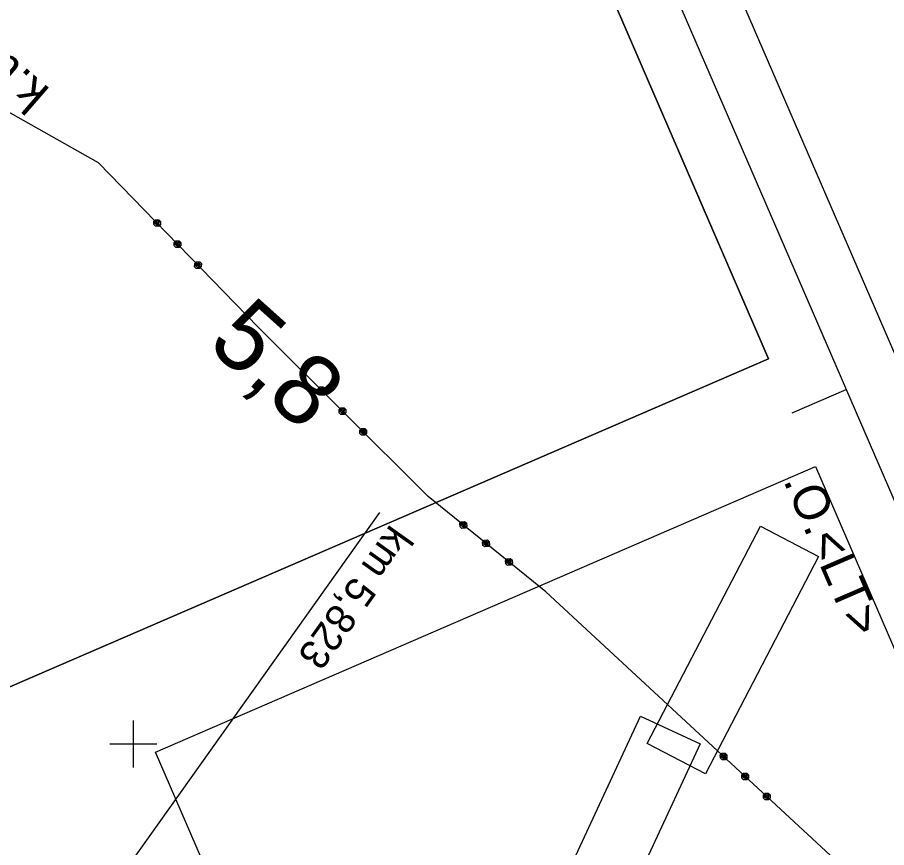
# Model space of a CAD drawing. Extents: x -866402 to -860377, y -1041908 to -1038598.
# Drawn here: x -864609.8 to -864536, y -1041408.8 to -1041338.3 of the extents above; entities that cross this region are included whole.
import ezdxf

# ---------------------------------------------------------------- set-up
doc = ezdxf.new("R2010")
doc.units = 0
for name, color, linetype in [('Vrstva 1', 7, 'Continuous'), ('Vrstva 21', 7, 'Continuous'), ('Vrstva 5', 7, 'Continuous'), ('Vrstva 55', 7, 'Continuous'), ('Vrstva 7', 7, 'Continuous'), ('Vrstva 9', 7, 'Continuous')]:
    doc.layers.add(name, color=color, linetype=linetype)

msp = doc.modelspace()

# ---------------------------------------------------------------- linework, layer by layer
at = {"layer": 'Vrstva 1'}
for p, q in [((-864602.95, -1041350.6), (-864622.98, -1041339.37)), ((-864602.95, -1041350.6), (-864622.98, -1041339.37)), ((-864589.39, -1041364.59), (-864602.95, -1041350.6)), ((-864589.39, -1041364.59), (-864602.95, -1041350.6)), ((-864598.264, -1041355.865), (-864598.26, -1041355.582)), ((-864598.264, -1041355.865), (-864598.26, -1041355.582)), ((-864598.125, -1041356.008), (-864598.264, -1041355.865)), ((-864598.125, -1041356.008), (-864598.264, -1041355.865)), ((-864598.26, -1041355.582), (-864598.116, -1041355.443)), ((-864598.26, -1041355.582), (-864598.116, -1041355.443)), ((-864598.192, -1041355.795), (-864597.905, -1041355.517)), ((-864598.192, -1041355.795), (-864597.905, -1041355.517)), ((-864598.19, -1041355.654), (-864598.192, -1041355.795)), ((-864598.19, -1041355.654), (-864598.192, -1041355.795)), ((-864598.046, -1041355.514), (-864598.19, -1041355.654)), ((-864598.046, -1041355.514), (-864598.19, -1041355.654)), ((-864597.842, -1041356.013), (-864598.125, -1041356.008)), ((-864597.842, -1041356.013), (-864598.125, -1041356.008)), ((-864597.835, -1041355.588), (-864598.123, -1041355.867)), ((-864597.835, -1041355.588), (-864598.123, -1041355.867)), ((-864598.116, -1041355.443), (-864597.833, -1041355.447)), ((-864598.116, -1041355.443), (-864597.833, -1041355.447)), ((-864597.766, -1041355.66), (-864598.053, -1041355.939)), ((-864597.766, -1041355.66), (-864598.053, -1041355.939)), ((-864598.053, -1041355.939), (-864597.912, -1041355.941)), ((-864598.053, -1041355.939), (-864597.912, -1041355.941)), ((-864597.912, -1041355.941), (-864597.768, -1041355.802)), ((-864597.912, -1041355.941), (-864597.768, -1041355.802)), ((-864597.905, -1041355.517), (-864597.766, -1041355.66)), ((-864597.905, -1041355.517), (-864597.766, -1041355.66)), ((-864597.698, -1041355.873), (-864597.842, -1041356.013)), ((-864597.698, -1041355.873), (-864597.842, -1041356.013)), ((-864597.833, -1041355.447), (-864597.694, -1041355.591)), ((-864597.833, -1041355.447), (-864597.694, -1041355.591)), ((-864597.694, -1041355.591), (-864597.698, -1041355.873)), ((-864597.694, -1041355.591), (-864597.698, -1041355.873)), ((-864596.524, -1041357.66), (-864596.52, -1041357.377)), ((-864596.524, -1041357.66), (-864596.52, -1041357.377)), ((-864596.52, -1041357.377), (-864596.376, -1041357.238)), ((-864596.52, -1041357.377), (-864596.376, -1041357.238)), ((-864596.452, -1041357.59), (-864596.165, -1041357.312)), ((-864596.452, -1041357.59), (-864596.165, -1041357.312)), ((-864596.45, -1041357.449), (-864596.452, -1041357.59)), ((-864596.45, -1041357.449), (-864596.452, -1041357.59)), ((-864596.307, -1041357.309), (-864596.45, -1041357.449)), ((-864596.307, -1041357.309), (-864596.45, -1041357.449)), ((-864596.095, -1041357.384), (-864596.383, -1041357.662)), ((-864596.095, -1041357.384), (-864596.383, -1041357.662)), ((-864596.376, -1041357.238), (-864596.093, -1041357.242)), ((-864596.376, -1041357.238), (-864596.093, -1041357.242)), ((-864596.026, -1041357.455), (-864596.313, -1041357.734)), ((-864596.026, -1041357.455), (-864596.313, -1041357.734)), ((-864596.165, -1041357.312), (-864596.026, -1041357.455)), ((-864596.165, -1041357.312), (-864596.026, -1041357.455)), ((-864596.093, -1041357.242), (-864595.954, -1041357.386)), ((-864596.093, -1041357.242), (-864595.954, -1041357.386)), ((-864595.954, -1041357.386), (-864595.959, -1041357.669)), ((-864595.954, -1041357.386), (-864595.959, -1041357.669)), ((-864596.385, -1041357.803), (-864596.524, -1041357.66)), ((-864596.385, -1041357.803), (-864596.524, -1041357.66)), ((-864596.102, -1041357.808), (-864596.385, -1041357.803)), ((-864596.102, -1041357.808), (-864596.385, -1041357.803)), ((-864596.313, -1041357.734), (-864596.172, -1041357.736)), ((-864596.313, -1041357.734), (-864596.172, -1041357.736)), ((-864596.172, -1041357.736), (-864596.028, -1041357.597)), ((-864596.172, -1041357.736), (-864596.028, -1041357.597)), ((-864595.959, -1041357.669), (-864596.102, -1041357.808)), ((-864595.959, -1041357.669), (-864596.102, -1041357.808)), ((-864594.784, -1041359.455), (-864594.78, -1041359.172)), ((-864594.784, -1041359.455), (-864594.78, -1041359.172)), ((-864594.645, -1041359.598), (-864594.784, -1041359.455)), ((-864594.645, -1041359.598), (-864594.784, -1041359.455)), ((-864594.78, -1041359.172), (-864594.636, -1041359.033)), ((-864594.78, -1041359.172), (-864594.636, -1041359.033)), ((-864594.712, -1041359.385), (-864594.425, -1041359.107)), ((-864594.712, -1041359.385), (-864594.425, -1041359.107)), ((-864594.71, -1041359.244), (-864594.712, -1041359.385)), ((-864594.71, -1041359.244), (-864594.712, -1041359.385)), ((-864594.567, -1041359.105), (-864594.71, -1041359.244)), ((-864594.567, -1041359.105), (-864594.71, -1041359.244)), ((-864594.362, -1041359.603), (-864594.645, -1041359.598)), ((-864594.362, -1041359.603), (-864594.645, -1041359.598)), ((-864594.356, -1041359.179), (-864594.643, -1041359.457)), ((-864594.356, -1041359.179), (-864594.643, -1041359.457)), ((-864594.636, -1041359.033), (-864594.353, -1041359.037)), ((-864594.636, -1041359.033), (-864594.353, -1041359.037)), ((-864594.286, -1041359.25), (-864594.573, -1041359.529)), ((-864594.286, -1041359.25), (-864594.573, -1041359.529)), ((-864594.573, -1041359.529), (-864594.432, -1041359.531)), ((-864594.573, -1041359.529), (-864594.432, -1041359.531)), ((-864594.432, -1041359.531), (-864594.288, -1041359.392)), ((-864594.432, -1041359.531), (-864594.288, -1041359.392)), ((-864594.425, -1041359.107), (-864594.286, -1041359.25)), ((-864594.425, -1041359.107), (-864594.286, -1041359.25)), ((-864594.219, -1041359.464), (-864594.362, -1041359.603)), ((-864594.219, -1041359.464), (-864594.362, -1041359.603)), ((-864594.353, -1041359.037), (-864594.214, -1041359.181)), ((-864594.353, -1041359.037), (-864594.214, -1041359.181)), ((-864594.214, -1041359.181), (-864594.219, -1041359.464)), ((-864594.214, -1041359.181), (-864594.219, -1041359.464)), ((-864574.94, -1041378.96), (-864589.39, -1041364.59)), ((-864574.94, -1041378.96), (-864589.39, -1041364.59)), ((-864584.291, -1041369.801), (-864584.15, -1041369.659)), ((-864584.291, -1041369.801), (-864584.15, -1041369.659)), ((-864584.291, -1041370.083), (-864584.291, -1041369.801)), ((-864584.291, -1041370.083), (-864584.291, -1041369.801)), ((-864584.149, -1041370.224), (-864584.291, -1041370.083)), ((-864584.149, -1041370.224), (-864584.291, -1041370.083)), ((-864584.079, -1041369.729), (-864584.22, -1041369.871)), ((-864584.22, -1041370.012), (-864583.938, -1041369.729)), ((-864584.079, -1041369.729), (-864584.22, -1041369.871)), ((-864584.22, -1041370.012), (-864583.938, -1041369.729)), ((-864584.22, -1041369.871), (-864584.22, -1041370.012)), ((-864584.22, -1041369.871), (-864584.22, -1041370.012)), ((-864584.15, -1041369.659), (-864583.867, -1041369.658)), ((-864584.15, -1041369.659), (-864583.867, -1041369.658)), ((-864583.867, -1041369.799), (-864584.149, -1041370.083)), ((-864583.867, -1041369.799), (-864584.149, -1041370.083)), ((-864583.796, -1041369.87), (-864584.078, -1041370.153)), ((-864583.796, -1041369.87), (-864584.078, -1041370.153)), ((-864583.938, -1041369.729), (-864583.796, -1041369.87)), ((-864583.938, -1041369.729), (-864583.796, -1041369.87)), ((-864583.937, -1041370.153), (-864583.796, -1041370.011)), ((-864583.937, -1041370.153), (-864583.796, -1041370.011)), ((-864583.867, -1041369.658), (-864583.726, -1041369.799)), ((-864583.867, -1041369.658), (-864583.726, -1041369.799)), ((-864583.725, -1041370.082), (-864583.866, -1041370.224)), ((-864583.725, -1041370.082), (-864583.866, -1041370.224)), ((-864583.726, -1041369.799), (-864583.725, -1041370.082)), ((-864583.726, -1041369.799), (-864583.725, -1041370.082)), ((-864544.025, -1041371.844), (-864539.44, -1041369.861)), ((-864583.866, -1041370.224), (-864584.149, -1041370.224)), ((-864583.866, -1041370.224), (-864584.149, -1041370.224)), ((-864584.078, -1041370.153), (-864583.937, -1041370.153)), ((-864584.078, -1041370.153), (-864583.937, -1041370.153)), ((-864582.519, -1041371.563), (-864582.378, -1041371.422)), ((-864582.519, -1041371.563), (-864582.378, -1041371.422)), ((-864582.518, -1041371.846), (-864582.519, -1041371.563)), ((-864582.518, -1041371.846), (-864582.519, -1041371.563)), ((-864582.307, -1041371.492), (-864582.448, -1041371.634)), ((-864582.307, -1041371.492), (-864582.448, -1041371.634)), ((-864582.447, -1041371.775), (-864582.165, -1041371.492)), ((-864582.447, -1041371.775), (-864582.165, -1041371.492)), ((-864582.378, -1041371.422), (-864582.095, -1041371.421)), ((-864582.378, -1041371.422), (-864582.095, -1041371.421)), ((-864582.094, -1041371.562), (-864582.376, -1041371.846)), ((-864582.094, -1041371.562), (-864582.376, -1041371.846)), ((-864582.165, -1041371.492), (-864582.023, -1041371.633)), ((-864582.165, -1041371.492), (-864582.023, -1041371.633)), ((-864582.095, -1041371.421), (-864581.953, -1041371.562)), ((-864582.095, -1041371.421), (-864581.953, -1041371.562)), ((-864581.953, -1041371.562), (-864581.952, -1041371.845)), ((-864581.953, -1041371.562), (-864581.952, -1041371.845)), ((-864582.376, -1041371.987), (-864582.518, -1041371.846)), ((-864582.376, -1041371.987), (-864582.518, -1041371.846)), ((-864582.448, -1041371.634), (-864582.447, -1041371.775)), ((-864582.448, -1041371.634), (-864582.447, -1041371.775)), ((-864582.093, -1041371.986), (-864582.376, -1041371.987)), ((-864582.093, -1041371.986), (-864582.376, -1041371.987)), ((-864582.023, -1041371.633), (-864582.306, -1041371.916)), ((-864582.023, -1041371.633), (-864582.306, -1041371.916)), ((-864582.306, -1041371.916), (-864582.164, -1041371.916)), ((-864582.306, -1041371.916), (-864582.164, -1041371.916)), ((-864582.164, -1041371.916), (-864582.023, -1041371.774)), ((-864582.164, -1041371.916), (-864582.023, -1041371.774)), ((-864581.952, -1041371.845), (-864582.093, -1041371.986)), ((-864581.952, -1041371.845), (-864582.093, -1041371.986)), ((-864580.746, -1041373.326), (-864580.605, -1041373.184)), ((-864580.746, -1041373.326), (-864580.605, -1041373.184)), ((-864580.745, -1041373.609), (-864580.746, -1041373.326)), ((-864580.745, -1041373.609), (-864580.746, -1041373.326)), ((-864580.603, -1041373.75), (-864580.745, -1041373.609)), ((-864580.603, -1041373.75), (-864580.745, -1041373.609)), ((-864580.534, -1041373.255), (-864580.675, -1041373.397)), ((-864580.675, -1041373.538), (-864580.393, -1041373.255)), ((-864580.534, -1041373.255), (-864580.675, -1041373.397)), ((-864580.675, -1041373.538), (-864580.393, -1041373.255)), ((-864580.675, -1041373.397), (-864580.675, -1041373.538)), ((-864580.675, -1041373.397), (-864580.675, -1041373.538)), ((-864580.605, -1041373.184), (-864580.322, -1041373.184)), ((-864580.605, -1041373.184), (-864580.322, -1041373.184)), ((-864580.322, -1041373.325), (-864580.604, -1041373.609)), ((-864580.322, -1041373.325), (-864580.604, -1041373.609)), ((-864580.321, -1041373.749), (-864580.603, -1041373.75)), ((-864580.321, -1041373.749), (-864580.603, -1041373.75)), ((-864580.251, -1041373.396), (-864580.533, -1041373.679)), ((-864580.251, -1041373.396), (-864580.533, -1041373.679)), ((-864580.533, -1041373.679), (-864580.391, -1041373.679)), ((-864580.533, -1041373.679), (-864580.391, -1041373.679)), ((-864580.393, -1041373.255), (-864580.251, -1041373.396)), ((-864580.393, -1041373.255), (-864580.251, -1041373.396)), ((-864580.391, -1041373.679), (-864580.25, -1041373.537)), ((-864580.391, -1041373.679), (-864580.25, -1041373.537)), ((-864580.322, -1041373.184), (-864580.18, -1041373.325)), ((-864580.322, -1041373.184), (-864580.18, -1041373.325)), ((-864580.18, -1041373.607), (-864580.321, -1041373.749)), ((-864580.18, -1041373.607), (-864580.321, -1041373.749)), ((-864580.18, -1041373.325), (-864580.18, -1041373.607)), ((-864580.18, -1041373.325), (-864580.18, -1041373.607)), ((-864564.95, -1041387.08), (-864574.94, -1041378.96)), ((-864564.95, -1041387.08), (-864574.94, -1041378.96)), ((-864572.258, -1041381.268), (-864572.132, -1041381.113)), ((-864572.258, -1041381.268), (-864572.132, -1041381.113)), ((-864572.054, -1041381.176), (-864572.18, -1041381.331)), ((-864572.054, -1041381.176), (-864572.18, -1041381.331)), ((-864572.166, -1041381.472), (-864571.914, -1041381.161)), ((-864572.166, -1041381.472), (-864571.914, -1041381.161)), ((-864572.132, -1041381.113), (-864571.85, -1041381.084)), ((-864572.132, -1041381.113), (-864571.85, -1041381.084)), ((-864571.914, -1041381.161), (-864571.758, -1041381.287)), ((-864571.914, -1041381.161), (-864571.758, -1041381.287)), ((-864571.85, -1041381.084), (-864571.695, -1041381.21)), ((-864571.85, -1041381.084), (-864571.695, -1041381.21)), ((-864572.229, -1041381.549), (-864572.258, -1041381.268)), ((-864572.229, -1041381.549), (-864572.258, -1041381.268)), ((-864572.074, -1041381.675), (-864572.229, -1041381.549)), ((-864572.074, -1041381.675), (-864572.229, -1041381.549)), ((-864572.18, -1041381.331), (-864572.166, -1041381.472)), ((-864572.18, -1041381.331), (-864572.166, -1041381.472)), ((-864571.836, -1041381.224), (-864572.088, -1041381.535)), ((-864571.836, -1041381.224), (-864572.088, -1041381.535)), ((-864571.792, -1041381.646), (-864572.074, -1041381.675)), ((-864571.792, -1041381.646), (-864572.074, -1041381.675)), ((-864571.758, -1041381.287), (-864572.011, -1041381.598)), ((-864571.758, -1041381.287), (-864572.011, -1041381.598)), ((-864572.011, -1041381.598), (-864571.87, -1041381.583)), ((-864572.011, -1041381.598), (-864571.87, -1041381.583)), ((-864571.87, -1041381.583), (-864571.744, -1041381.428)), ((-864571.87, -1041381.583), (-864571.744, -1041381.428)), ((-864571.666, -1041381.491), (-864571.792, -1041381.646)), ((-864571.666, -1041381.491), (-864571.792, -1041381.646)), ((-864571.695, -1041381.21), (-864571.666, -1041381.491)), ((-864571.695, -1041381.21), (-864571.666, -1041381.491)), ((-864570.318, -1041382.845), (-864570.192, -1041382.69)), ((-864570.318, -1041382.845), (-864570.192, -1041382.69)), ((-864570.289, -1041383.126), (-864570.318, -1041382.845)), ((-864570.289, -1041383.126), (-864570.318, -1041382.845)), ((-864570.134, -1041383.252), (-864570.289, -1041383.126)), ((-864570.134, -1041383.252), (-864570.289, -1041383.126)), ((-864570.114, -1041382.753), (-864570.24, -1041382.908)), ((-864570.114, -1041382.753), (-864570.24, -1041382.908)), ((-864570.24, -1041382.908), (-864570.226, -1041383.049)), ((-864570.24, -1041382.908), (-864570.226, -1041383.049)), ((-864570.226, -1041383.049), (-864569.974, -1041382.738)), ((-864570.226, -1041383.049), (-864569.974, -1041382.738)), ((-864570.192, -1041382.69), (-864569.91, -1041382.661)), ((-864570.192, -1041382.69), (-864569.91, -1041382.661)), ((-864569.896, -1041382.801), (-864570.148, -1041383.112)), ((-864569.896, -1041382.801), (-864570.148, -1041383.112)), ((-864569.852, -1041383.223), (-864570.134, -1041383.252)), ((-864569.852, -1041383.223), (-864570.134, -1041383.252)), ((-864569.818, -1041382.864), (-864570.071, -1041383.175)), ((-864569.818, -1041382.864), (-864570.071, -1041383.175)), ((-864570.071, -1041383.175), (-864569.93, -1041383.16)), ((-864570.071, -1041383.175), (-864569.93, -1041383.16)), ((-864569.974, -1041382.738), (-864569.818, -1041382.864)), ((-864569.974, -1041382.738), (-864569.818, -1041382.864)), ((-864569.93, -1041383.16), (-864569.804, -1041383.005)), ((-864569.93, -1041383.16), (-864569.804, -1041383.005)), ((-864569.91, -1041382.661), (-864569.755, -1041382.787)), ((-864569.91, -1041382.661), (-864569.755, -1041382.787)), ((-864569.726, -1041383.068), (-864569.852, -1041383.223)), ((-864569.726, -1041383.068), (-864569.852, -1041383.223)), ((-864569.755, -1041382.787), (-864569.726, -1041383.068)), ((-864569.755, -1041382.787), (-864569.726, -1041383.068)), ((-864568.378, -1041384.422), (-864568.252, -1041384.266)), ((-864568.378, -1041384.422), (-864568.252, -1041384.266)), ((-864568.349, -1041384.703), (-864568.378, -1041384.422)), ((-864568.349, -1041384.703), (-864568.378, -1041384.422)), ((-864568.194, -1041384.829), (-864568.349, -1041384.703)), ((-864568.194, -1041384.829), (-864568.349, -1041384.703)), ((-864568.174, -1041384.33), (-864568.3, -1041384.485)), ((-864568.174, -1041384.33), (-864568.3, -1041384.485)), ((-864568.3, -1041384.485), (-864568.286, -1041384.625)), ((-864568.3, -1041384.485), (-864568.286, -1041384.625)), ((-864568.286, -1041384.625), (-864568.034, -1041384.315)), ((-864568.286, -1041384.625), (-864568.034, -1041384.315)), ((-864568.252, -1041384.266), (-864567.97, -1041384.237)), ((-864568.252, -1041384.266), (-864567.97, -1041384.237)), ((-864567.956, -1041384.378), (-864568.208, -1041384.688)), ((-864567.956, -1041384.378), (-864568.208, -1041384.688)), ((-864567.912, -1041384.8), (-864568.194, -1041384.829)), ((-864567.912, -1041384.8), (-864568.194, -1041384.829)), ((-864567.878, -1041384.441), (-864568.131, -1041384.752)), ((-864567.878, -1041384.441), (-864568.131, -1041384.752)), ((-864568.131, -1041384.752), (-864567.99, -1041384.737)), ((-864568.131, -1041384.752), (-864567.99, -1041384.737)), ((-864568.034, -1041384.315), (-864567.878, -1041384.441)), ((-864568.034, -1041384.315), (-864567.878, -1041384.441)), ((-864567.99, -1041384.737), (-864567.864, -1041384.582)), ((-864567.99, -1041384.737), (-864567.864, -1041384.582)), ((-864567.97, -1041384.237), (-864567.815, -1041384.364)), ((-864567.97, -1041384.237), (-864567.815, -1041384.364)), ((-864567.786, -1041384.645), (-864567.912, -1041384.8)), ((-864567.786, -1041384.645), (-864567.912, -1041384.8)), ((-864567.815, -1041384.364), (-864567.786, -1041384.645)), ((-864567.815, -1041384.364), (-864567.786, -1041384.645)), ((-864530.92, -1041418.58), (-864564.95, -1041387.08)), ((-864530.92, -1041418.58), (-864564.95, -1041387.08)), ((-864550.131, -1041400.933), (-864549.995, -1041400.786)), ((-864550.131, -1041400.933), (-864549.995, -1041400.786)), ((-864550.12, -1041401.216), (-864550.131, -1041400.933)), ((-864550.12, -1041401.216), (-864550.131, -1041400.933)), ((-864549.921, -1041400.854), (-864550.057, -1041401.001)), ((-864549.921, -1041400.854), (-864550.057, -1041401.001)), ((-864550.057, -1041401.001), (-864550.052, -1041401.142)), ((-864550.057, -1041401.001), (-864550.052, -1041401.142)), ((-864550.052, -1041401.142), (-864549.78, -1041400.849)), ((-864550.052, -1041401.142), (-864549.78, -1041400.849)), ((-864549.995, -1041400.786), (-864549.712, -1041400.775)), ((-864549.995, -1041400.786), (-864549.712, -1041400.775)), ((-864549.707, -1041400.917), (-864549.978, -1041401.21)), ((-864549.707, -1041400.917), (-864549.978, -1041401.21)), ((-864549.633, -1041400.984), (-864549.905, -1041401.278)), ((-864549.633, -1041400.984), (-864549.905, -1041401.278)), ((-864549.78, -1041400.849), (-864549.633, -1041400.984)), ((-864549.78, -1041400.849), (-864549.633, -1041400.984)), ((-864549.712, -1041400.775), (-864549.565, -1041400.911)), ((-864549.712, -1041400.775), (-864549.565, -1041400.911)), ((-864549.565, -1041400.911), (-864549.554, -1041401.194)), ((-864549.565, -1041400.911), (-864549.554, -1041401.194)), ((-864549.973, -1041401.351), (-864550.12, -1041401.216)), ((-864549.973, -1041401.351), (-864550.12, -1041401.216)), ((-864549.69, -1041401.341), (-864549.973, -1041401.351)), ((-864549.69, -1041401.341), (-864549.973, -1041401.351)), ((-864549.905, -1041401.278), (-864549.764, -1041401.273)), ((-864549.905, -1041401.278), (-864549.764, -1041401.273)), ((-864549.764, -1041401.273), (-864549.628, -1041401.126)), ((-864549.764, -1041401.273), (-864549.628, -1041401.126)), ((-864549.554, -1041401.194), (-864549.69, -1041401.341)), ((-864549.554, -1041401.194), (-864549.69, -1041401.341)), ((-864548.296, -1041402.631), (-864548.16, -1041402.484)), ((-864548.296, -1041402.631), (-864548.16, -1041402.484)), ((-864548.087, -1041402.552), (-864548.223, -1041402.699)), ((-864548.087, -1041402.552), (-864548.223, -1041402.699)), ((-864548.217, -1041402.84), (-864547.945, -1041402.547)), ((-864548.217, -1041402.84), (-864547.945, -1041402.547)), ((-864548.16, -1041402.484), (-864547.877, -1041402.473)), ((-864548.16, -1041402.484), (-864547.877, -1041402.473)), ((-864547.945, -1041402.547), (-864547.799, -1041402.683)), ((-864547.945, -1041402.547), (-864547.799, -1041402.683)), ((-864547.877, -1041402.473), (-864547.731, -1041402.609)), ((-864547.877, -1041402.473), (-864547.731, -1041402.609)), ((-864548.285, -1041402.914), (-864548.296, -1041402.631)), ((-864548.285, -1041402.914), (-864548.296, -1041402.631)), ((-864548.138, -1041403.05), (-864548.285, -1041402.914)), ((-864548.138, -1041403.05), (-864548.285, -1041402.914)), ((-864548.223, -1041402.699), (-864548.217, -1041402.84)), ((-864548.223, -1041402.699), (-864548.217, -1041402.84)), ((-864547.872, -1041402.615), (-864548.144, -1041402.908)), ((-864547.872, -1041402.615), (-864548.144, -1041402.908)), ((-864547.856, -1041403.039), (-864548.138, -1041403.05)), ((-864547.856, -1041403.039), (-864548.138, -1041403.05)), ((-864547.799, -1041402.683), (-864548.07, -1041402.976)), ((-864547.799, -1041402.683), (-864548.07, -1041402.976)), ((-864548.07, -1041402.976), (-864547.929, -1041402.971)), ((-864548.07, -1041402.976), (-864547.929, -1041402.971)), ((-864547.929, -1041402.971), (-864547.793, -1041402.824)), ((-864547.929, -1041402.971), (-864547.793, -1041402.824)), ((-864547.72, -1041402.892), (-864547.856, -1041403.039)), ((-864547.72, -1041402.892), (-864547.856, -1041403.039)), ((-864547.731, -1041402.609), (-864547.72, -1041402.892)), ((-864547.731, -1041402.609), (-864547.72, -1041402.892)), ((-864546.461, -1041404.329), (-864546.325, -1041404.183)), ((-864546.461, -1041404.329), (-864546.325, -1041404.183)), ((-864546.45, -1041404.612), (-864546.461, -1041404.329)), ((-864546.45, -1041404.612), (-864546.461, -1041404.329)), ((-864546.304, -1041404.748), (-864546.45, -1041404.612)), ((-864546.304, -1041404.748), (-864546.45, -1041404.612)), ((-864546.252, -1041404.251), (-864546.388, -1041404.397)), ((-864546.252, -1041404.251), (-864546.388, -1041404.397)), ((-864546.388, -1041404.397), (-864546.382, -1041404.539)), ((-864546.388, -1041404.397), (-864546.382, -1041404.539)), ((-864546.382, -1041404.539), (-864546.111, -1041404.245)), ((-864546.382, -1041404.539), (-864546.111, -1041404.245)), ((-864546.325, -1041404.183), (-864546.043, -1041404.172)), ((-864546.325, -1041404.183), (-864546.043, -1041404.172)), ((-864546.037, -1041404.313), (-864546.309, -1041404.607)), ((-864546.037, -1041404.313), (-864546.309, -1041404.607)), ((-864546.021, -1041404.737), (-864546.304, -1041404.748)), ((-864546.021, -1041404.737), (-864546.304, -1041404.748)), ((-864545.964, -1041404.381), (-864546.236, -1041404.675)), ((-864545.964, -1041404.381), (-864546.236, -1041404.675)), ((-864546.236, -1041404.675), (-864546.094, -1041404.669)), ((-864546.236, -1041404.675), (-864546.094, -1041404.669)), ((-864546.111, -1041404.245), (-864545.964, -1041404.381)), ((-864546.111, -1041404.245), (-864545.964, -1041404.381)), ((-864546.094, -1041404.669), (-864545.959, -1041404.522)), ((-864546.094, -1041404.669), (-864545.959, -1041404.522)), ((-864546.043, -1041404.172), (-864545.896, -1041404.308)), ((-864546.043, -1041404.172), (-864545.896, -1041404.308)), ((-864545.885, -1041404.59), (-864546.021, -1041404.737)), ((-864545.885, -1041404.59), (-864546.021, -1041404.737)), ((-864545.896, -1041404.308), (-864545.885, -1041404.59)), ((-864545.896, -1041404.308), (-864545.885, -1041404.59))]:
    msp.add_line(p, q, dxfattribs=at)
for points in [[(-865224.278, -1040522.071), (-864724.074, -1041678.518), (-864451.49, -1041560.616), (-864951.694, -1040404.169)], [(-864954.298, -1040410.743), (-864458.064, -1041558.012), (-864721.47, -1041671.944), (-865217.704, -1040524.675)], [(-865211.136, -1040527.276), (-864800.251, -1041477.223), (-864546.014, -1041367.257), (-864956.899, -1040417.31)], [(-864956.899, -1040417.31), (-864546.014, -1041367.257), (-864800.251, -1041477.223), (-865211.136, -1040527.276)]]:
    msp.add_lwpolyline(points, close=True, dxfattribs=at)
at = {"layer": 'Vrstva 21'}
for points in [[(-864598.121, -1041400.684), (-864542.042, -1041376.428), (-864494.403, -1041486.567), (-864550.482, -1041510.823)], [(-864546.72, -1041381.478), (-864541.77, -1041384.053), (-864551.391, -1041402.546), (-864556.341, -1041399.971)], [(-864546.72, -1041381.478), (-864541.77, -1041384.053), (-864551.391, -1041402.546), (-864556.341, -1041399.971)], [(-864556.899, -1041397.644), (-864551.84, -1041399.996), (-864560.627, -1041418.9), (-864565.686, -1041416.548)]]:
    msp.add_lwpolyline(points, close=True, dxfattribs=at)
at = {"layer": 'Vrstva 5'}
for p, q in [((-864600, -1041398), (-864600, -1041402)), ((-864602, -1041400), (-864598, -1041400))]:
    msp.add_line(p, q, dxfattribs=at)
at = {"layer": 'Vrstva 9'}
msp.add_line((-864611.849, -1041426.436), (-864579.049, -1041380.327), dxfattribs=at)

# ---------------------------------------------------------------- texts
at = {"layer": 'Vrstva 1'}
msp.add_text('.O.<LT>', height=3, rotation=293.39015, dxfattribs=at).set_placement((-864544.795, -1041377.619))
at = {"layer": 'Vrstva 55'}
msp.add_text('k.ú.Stanoviště u ML', height=3, rotation=139.05559, dxfattribs=at).set_placement((-864606.973, -1041344.395))
at = {"layer": 'Vrstva 7'}
msp.add_text('5,8', height=6, rotation=318.15059, dxfattribs=at).set_placement((-864593.853, -1041366.15))
at = {"layer": 'Vrstva 9'}
msp.add_text('km 5,823', height=2.5, rotation=234.5733, dxfattribs=at).set_placement((-864578.137, -1041381.246))

doc.saveas('drawing.dxf')
